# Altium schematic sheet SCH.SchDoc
size A4
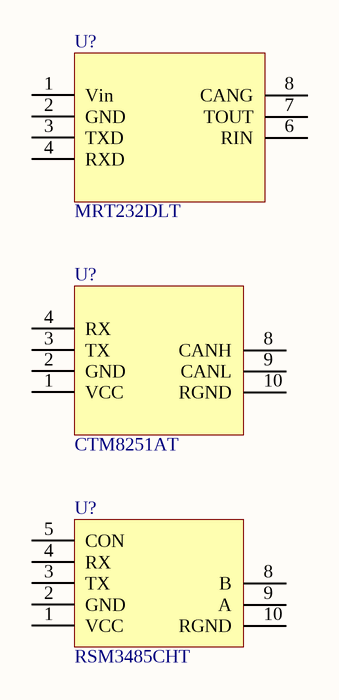
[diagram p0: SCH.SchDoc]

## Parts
(Parts that share a designator on the sheet are numbered #1, #2 ... from top to bottom, then left to right.)
U?#1  MRT232DLT  [RS485]
U?#2  CTM8251AT  [RSM3845]
U?#3  RSM3485CHT  [RSM3845]

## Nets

Not connected (* = marked no-connect by the designer): U?#1 1(Vin) 2(GND) 3(TXD) 4(RXD) 6(RIN) 7(TOUT) 8(CANG); U?#2 1(VCC) 2(GND) 3(TX) 4(RX) 8(CANH) 9(CANL) 10(RGND); U?#3 1(VCC) 2(GND) 3(TX) 4(RX) 5(CON) 8(B) 9(A) 10(RGND)

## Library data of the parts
U?#1 = MRT232DLT: 36 Pin AT Connector
U?#3 = RSM485CHT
